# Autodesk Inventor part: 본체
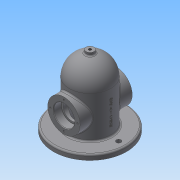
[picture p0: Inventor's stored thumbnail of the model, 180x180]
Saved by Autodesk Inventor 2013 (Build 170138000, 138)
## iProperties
Created: 2019-11
Part Number: 본체
Material: 일반
Document SubType Name: Modeling
Designer: Administrator
Density: 1 g/cm^3
Author: Administrator
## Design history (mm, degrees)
sketch "스케치1"
  geometry: C1 r 70 at (0, 0); 1 further point
  constraints: 1 centre point, 1 coincident
  dimensions: "d0" = 140 diameter of C1
extrude "돌출1" new body sketch "스케치1" distance "d1" = 10; taper "d2" = 0 deg
sketch "스케치2"
  geometry: C1 r 70 at (0, 0) reference; C2 r 40 at (0, 0)
  constraints: 1 centre point, 1 coincident
  dimensions: "d3" = 80 diameter of C2
extrude "돌출2" join sketch "스케치2" distance "d4" = 80; taper "d5" = 0 deg
sketch "스케치3"
  geometry: L1 (-70, 0)-(-70, 10) reference; L2 (-70, 10)-(-40, 10) reference; L3 (-40, 10)-(-40, 90) reference; L4 (-40, 90)-(40, 90) reference; L5 (40, 90)-(40, 10) reference; L6 (40, 10)-(70, 10) reference; L7 (70, 10)-(70, 0) reference; L8 (70, 0)-(-70, 0) reference; A1 r 40 centre (0, 90) between (40, 90) and (-40, 90); 1 further point
  constraints: 2 end point, 2 point on circle, 1 centre point, 1 midpoint
revolve "회전1" sketch "스케치3" stored, may be unused: angle "d6" = 90 deg
node "작업 평면1"
sketch "스케치4"
  geometry: L1 (70, 10)-(-70, 10) reference; L2 (-70, 0)-(70, 0) reference; L3 (40, 90)-(-40, 90) reference; L4 (-40, 10)-(40, 10) reference; C1 r 31 at (0, 50); 2 further points
  constraints: 1 centre point, 1 midpoint, 1 vertical alignment
  dimensions: "d8" = 62 diameter of C1; "d10" = 50 distance from line of C1.centre L2
extrude "돌출3" join sketch "스케치4" stored distance "d11" = 90; taper "d12" = 0 deg
sketch "스케치5"
  geometry: C1 r 31 at (0, 0) reference; C2 r 16.5 at (0, 0); 1 further point
  constraints: 1 centre point, 1 coincident
  dimensions: "d13" = 33 diameter of C2
extrude "돌출4" cut sketch "스케치5" stored distance "d14" = 90; taper "d15" = 0 deg
sketch "스케치7"
  geometry: C1 r 16.5 at (0, 0) reference; C2 r 31 at (0, 0) reference; C3 r 20 at (0, 0); 1 further point
  constraints: 1 centre point, 1 coincident
  dimensions: "d16" = 40 diameter of C3
extrude "돌출5" cut sketch "스케치7" distance "d17" = 15; taper "d18" = 0 deg
sketch "스케치8"
  geometry: C1 r 16.5 at (0, 0) reference; C2 r 31 at (0, 0) reference; C3 r 20 at (0, 0); 1 further point
  constraints: 1 centre point, 1 coincident
  dimensions: "d19" = 40 diameter of C3
extrude "돌출6" cut sketch "스케치8" distance "d20" = 15; taper "d21" = 0 deg
chamfer "모따기1" distance "d22" = 1; stored, may be unused: second distance "d23" = 2, angle "d24" = 45 deg
fillet "모깎기1" dims "d25" = 0.3
sketch "스케치9"
  geometry: L1 (35, 69.7)-(35, 66.5) reference; L2 (35, 66.5)-(-35, 66.5) reference; L3 (-35, 66.5)-(-35, 69.7) reference; L4 (-35.3, 70)-(-49, 70) reference; L5 (-49, 70)-(-50, 71) reference; L6 (-50, 71)-(-50, 81) reference; L7 (-50, 81)-(-40, 81) reference; L8 (-40, 81)-(-40, 90) reference; L9 (40, 90)-(40, 81) reference; L10 (40, 81)-(50, 81) reference; L11 (50, 81)-(50, 71) reference; L12 (50, 71)-(49, 70) reference; L13 (49, 70)-(35.3, 70) reference; L14 (-70, 0)-(-70, 10) reference; L15 (-70, 10)-(-40, 10) reference; L16 (-40, 10)-(-40, 19) reference; L17 (-40, 19)-(-50, 19) reference; L18 (-50, 19)-(-50, 29) reference; L19 (-50, 29)-(-49, 30) reference; L20 (-49, 30)-(-35.3, 30) reference; L21 (-35, 30.3)-(-35, 33.5) reference; L22 (-35, 33.5)-(35, 33.5) reference; L23 (35, 33.5)-(35, 30.3) reference; L24 (35.3, 30)-(49, 30) reference; L25 (49, 30)-(50, 29) reference; L26 (50, 29)-(50, 19) reference; L27 (50, 19)-(40, 19) reference; L28 (40, 19)-(40, 10) reference; L29 (40, 10)-(70, 10) reference; L30 (70, 10)-(70, 0) reference; L31 (70, 0)-(-70, 0) reference; L32 (0, 0)-(-30, 0); L33 (-30, 0)-(-30, 90); L34 (-30, 90)-(0, 90); L35 (0, 90)-(0, 0); A1 r 0.3 centre (35.3, 69.7) between (35.3, 70) and (35, 69.7) reference; A2 r 0.3 centre (-35.3, 69.7) between (-35, 69.7) and (-35.3, 70) reference; A3 r 40 centre (0, 90) between (40, 90) and (0, 130) reference; A4 r 40 centre (0, 90) between (0, 130) and (-40, 90) reference; A5 r 0.3 centre (-35.3, 30.3) between (-35.3, 30) and (-35, 30.3) reference; A6 r 0.3 centre (35.3, 30.3) between (35, 30.3) and (35.3, 30) reference
  constraints: 8 end point, 2 vertical, 1 horizontal, 1 point on line
  dimensions: "d26" = 90 distance of L34.end L32.start; "d27" = 60 diameter of L33 L35
revolve "회전2" sketch "스케치9" stored, may be unused: angle "d28" = 90 deg
sketch "스케치10"
  geometry: L1 (35, 69.7)-(35, 66.5) reference; L2 (35, 66.5)-(30, 66.5) reference; L3 (30, 66.5)-(30, 90) reference; L4 (30, 90)-(-30, 90) reference; L5 (-30, 90)-(-30, 66.5) reference; L6 (-30, 66.5)-(-35, 66.5) reference; L7 (-35, 66.5)-(-35, 69.7) reference; L8 (-35.3, 70)-(-49, 70) reference; L9 (-49, 70)-(-50, 71) reference; L10 (-50, 71)-(-50, 81) reference; L11 (-50, 81)-(-40, 81) reference; L12 (-40, 81)-(-40, 90) reference; L13 (40, 90)-(40, 81) reference; L14 (40, 81)-(50, 81) reference; L15 (50, 81)-(50, 71) reference; L16 (50, 71)-(49, 70) reference; L17 (49, 70)-(35.3, 70) reference; L18 (70, 10)-(70, 0) reference; L19 (70, 0)-(30, 0) reference; L20 (30, 0)-(30, 33.5) reference; L21 (30, 33.5)-(35, 33.5) reference; L22 (35, 33.5)-(35, 30.3) reference; L23 (35.3, 30)-(49, 30) reference; L24 (49, 30)-(50, 29) reference; L25 (50, 29)-(50, 19) reference; L26 (50, 19)-(40, 19) reference; L27 (40, 19)-(40, 10) reference; L28 (40, 10)-(70, 10) reference; L29 (-70, 0)-(-70, 10) reference; L30 (-70, 10)-(-40, 10) reference; L31 (-40, 10)-(-40, 19) reference; L32 (-40, 19)-(-50, 19) reference; L33 (-50, 19)-(-50, 29) reference; L34 (-50, 29)-(-49, 30) reference; L35 (-49, 30)-(-35.3, 30) reference; L36 (-35, 30.3)-(-35, 33.5) reference; L37 (-35, 33.5)-(-30, 33.5) reference; L38 (-30, 33.5)-(-30, 0) reference; L39 (-30, 0)-(-70, 0) reference; A1 r 0.3 centre (35.3, 69.7) between (35.3, 70) and (35, 69.7) reference; A2 r 0.3 centre (-35.3, 69.7) between (-35, 69.7) and (-35.3, 70) reference; A3 r 40 centre (0, 90) between (40, 90) and (0, 130) reference; A4 r 40 centre (0, 90) between (0, 130) and (-40, 90) reference; A5 r 0.3 centre (35.3, 30.3) between (35, 30.3) and (35.3, 30) reference; A6 r 0.3 centre (-35.3, 30.3) between (-35.3, 30) and (-35, 30.3) reference; A7 r 30 centre (0, 90) between (30, 90) and (-30, 90); 1 further point
  constraints: 2 end point, 2 point on circle, 1 centre point, 1 coincident, 1 midpoint
revolve "회전3" sketch "스케치10" stored, may be unused: angle "d29" = 90 deg
node "작업 평면2"
sketch "스케치11"
  geometry: C1 r 7.5 at (0, 0); 1 further point
  constraints: 1 centre point, 1 coincident
  dimensions: "d31" = 15 diameter of C1
extrude "돌출7" join sketch "스케치11" stored distance "d33" = 15; taper "d34" = 0 deg
sketch "스케치12"
  geometry: C1 r 7.5 at (0, 0) reference
hole "구멍1" sketch "스케치12" at (0, 0) diameter "d35" = 5.188; stored, may be unused: countersink angle "d39" = 90 deg, drill point angle "d41" = 118 deg; dims "d36" = 6, "d37" = 4, "d38" = 2, "d40" = 20.5
fillet "모깎기2" dims "d42" = 3
fillet "모깎기3" dims "d43" = 3
sketch "스케치14" dims "d46" = 110
  geometry: C1 r 43 at (0, 0) reference; C2 r 4.5 at (0, 55); 1 further point
  constraints: 2 vertical alignment, 1 centre point, 1 coincident, 2 other
  dimensions: "d47" = 9 diameter of C2
extrude "돌출8" cut sketch "스케치14" stored distance "d48" = 15; taper "d49" = 0 deg
sketch "스케치15" dims "d50" = 52
  geometry: C1 r 21 at (0, 0) reference; 3 further points
  constraints: 2 horizontal alignment, 1 coincident, 2 other
hole "구멍2" sketch "스케치15" at (26, 0) diameter "d51" = 3.242; stored, may be unused: countersink angle "d55" = 90 deg, drill point angle "d57" = 118 deg; dims "d52" = 8, "d53" = 4, "d54" = 2, "d56" = 10
node "작업 평면3"
sketch "스케치16"
  geometry: L1 (0, 3)-(0, 80) reference; L2 (-53.749, 0)-(-15.78, 0) reference; L3 (-57.446, -10)-(-57.446, -3) reference; L4 (57.446, -10)-(-57.446, -10) reference; L5 (57.446, -3)-(57.446, -10) reference; L6 (15.78, 0)-(53.749, 0) reference; 2 further points
  constraints: 1 vertical alignment, 5 other
  dimensions: "d61" = 50 distance from line of point (0, 40) L4
feature "엠보싱1" sketch "스케치16" dims "d62" = 0.5, "d63" = 0
node "솔리드1"
mirror "대칭1"
mirror "대칭2"
pattern_circular "원형 패턴1" dims angle "d59" = 360 deg
mirror "대칭3"
node "투영된 루프1"
node "투영된 루프2"
node "절단 모서리 투영1"
node "절단 모서리 투영3"
node "절단 모서리 투영4"
node "절단 모서리 투영5"
other parameters: "d30" = -135
